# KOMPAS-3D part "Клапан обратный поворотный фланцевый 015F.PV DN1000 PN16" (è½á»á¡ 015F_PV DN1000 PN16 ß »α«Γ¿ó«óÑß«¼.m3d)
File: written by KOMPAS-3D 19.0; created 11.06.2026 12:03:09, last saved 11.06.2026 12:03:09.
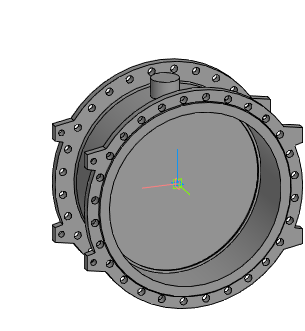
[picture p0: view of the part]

Document properties: Автор: Энергия; Полное имя файла: Z:\3.Личные\kachalov\001_3d для проектировщиков\5.5 Тип 015F.PV Клапан обратный поворотный с двумя эксцентриками\_stp_Клапан 015F.PV DN300-DN1200 с противовесом\Клапан 015F_PV DN1000 PN16 с противовесом.m3d

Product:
- Part/product: Клапан обратный поворотный фланцевый 015F.PV DN1000 PN16

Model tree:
1. Операция без истории:1
2. Сплайн:1
     Координата Y = 30; Координата Z = 500; Вес = 1; Координата X = 1000; Координата Y = 161.652; Координата Z = 500; Вес = 0.333333; Координата X = 1000; Координата Y = 161.652; Координата Z = -500; Вес = 0.333333; Координата Y = 30; Координата Z = -500; Вес = 1; Координата X = -1000; Координата Y = -101.652; Координата Z = -500; Вес = 0.333333; Координата X = -1000; Координата Y = -101.652; Координата Z = 500; Вес = 0.333333; Порядок = 4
